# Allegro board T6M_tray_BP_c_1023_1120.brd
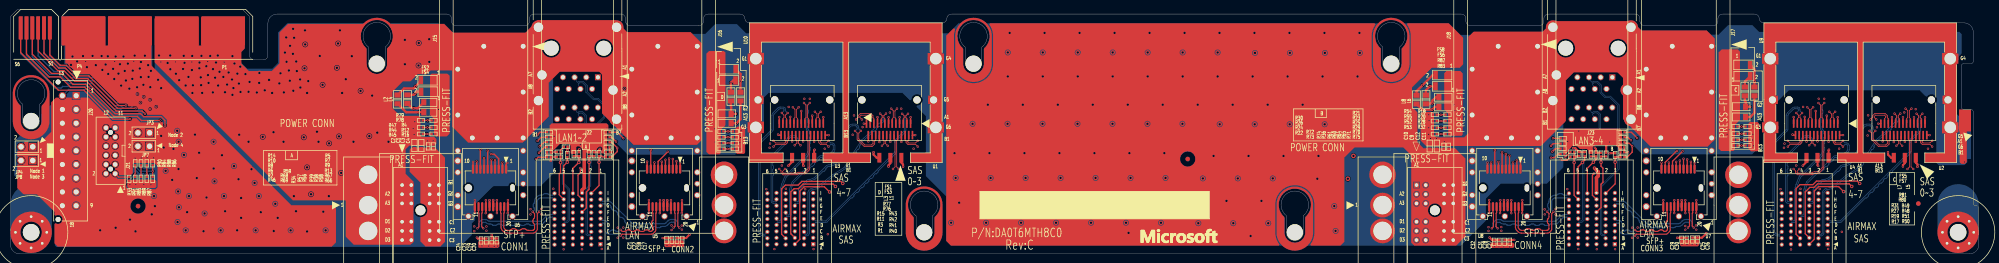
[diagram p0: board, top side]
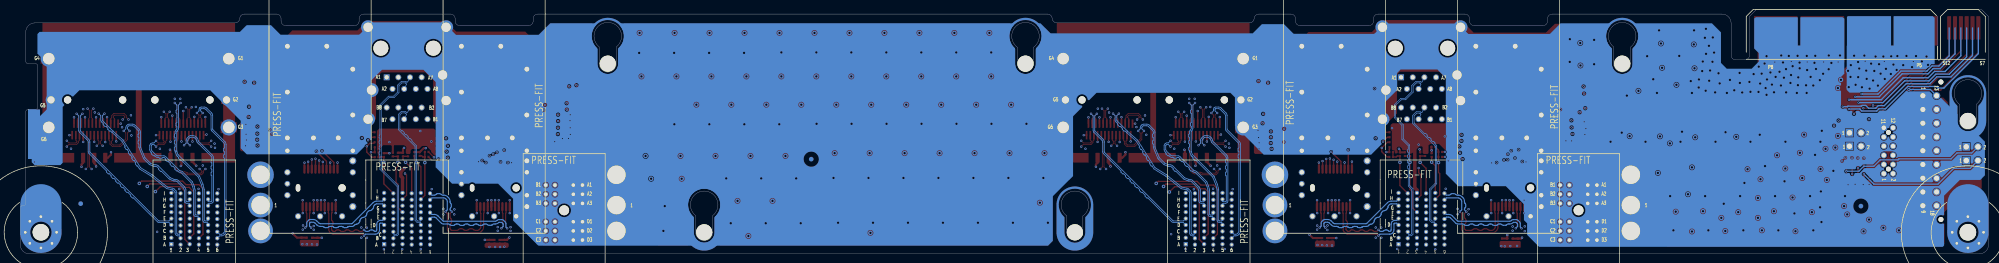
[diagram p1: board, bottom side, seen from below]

Outline 428.81 x 53.3 mm; copper layers: TOP, GND, IN1, VCC, VCC1, IN2, GND1, BOTTOM. Coordinates in mm from the lower left corner of the outline.
Outline path: 0,51.8 0,2 arc(0.59,0.59) 2,0 426.81,0 arc(428.22,0.59) 428.81,2 428.81,10 arc(428.66,10.35) 428.31,10.5 428.11,10.5 arc(427.76,10.65) 427.61,11 427.61,31 arc(427.46,31.35) 427.11,31.5 425.51,31.5 arc(425.16,31.65) 425.01,32 425.01,41 arc(425.16,41.35) 425.51,41.5 427.11,41.5 arc(427.46,41.65) 427.61,42 427.61,48.39 arc(427.02,49.8) 425.61,50.39 381.99,50.39 381.61,50.46 381.29,50.68 381.07,51 380.98,51.38 380.91,51.7 380.7,52.03 380.37,52.24 379.99,52.32 372.99,52.32 arc(372.28,52.03) 371.99,51.32 371.99,50.8 arc(371.7,50.09) 370.99,49.8 355.99,49.8 arc(355.28,50.09) 354.99,50.8 354.99,51.32 arc(354.7,52.03) 353.99,52.32 335.07,52.32 arc(334.36,52.03) 334.07,51.32 334.07,50.8 arc(333.78,50.09) 333.07,49.8 318.07,49.8 arc(317.36,50.09) 317.07,50.8 317.07,51.32 arc(316.78,52.03) 316.07,52.32 204.99,52.32 204.61,52.24 204.28,52.03 204.07,51.7 204,51.38 203.91,51 203.69,50.68 203.37,50.46 202.99,50.39 160.99,50.39 160.61,50.46 160.29,50.68 160.07,51 159.98,51.38 159.91,51.7 159.7,52.03 159.37,52.24 158.99,52.32 151.99,52.32 arc(151.28,52.03) 150.99,51.32 150.99,50.8 arc(150.7,50.09) 149.99,49.8 134.99,49.8 arc(134.28,50.09) 133.99,50.8 133.99,51.32 arc(133.7,52.03) 132.99,52.32 114.07,52.32 arc(113.36,52.03) 113.07,51.32 113.07,50.8 arc(112.78,50.09) 112.07,49.8 97.07,49.8 arc(96.36,50.09) 96.07,50.8 96.07,51.32 arc(95.78,52.03) 95.07,52.32 58.08,52.32 arc(56.67,51.73) 56.08,50.32 56.08,43.32 arc(55.79,42.61) 55.08,42.32 53.08,42.32 arc(52.37,42.61) 52.08,43.32 52.08,51.8 50.58,53.3 12.65,53.3 11.15,51.8 11.15,42.65 arc(10.8,42.3) 10.45,42.65 10.45,51.8 9.45,52.8 8.95,53.3 1.5,53.3 1,52.8 0,51.8 ; 2.65,32.64 arc(4.5,38) 6.35,32.64 6.35,29 arc(4.5,27.15) 2.65,29 2.65,32.64 ; 77.96,45.14 arc(79.81,50.5) 81.66,45.14 81.66,41.5 arc(79.81,39.65) 77.96,41.5 77.96,45.14 ; 197.3,8.26 arc(199.05,13.7) 200.8,8.26 200.8,4.7 arc(199.05,2.95) 197.3,4.7 197.3,8.26 ; 208.06,45.06 arc(209.81,50.5) 211.56,45.06 211.56,41.5 arc(209.81,39.75) 208.06,41.5 208.06,45.06 ; 277.96,8.34 arc(279.81,13.7) 281.66,8.34 281.66,4.7 arc(279.81,2.85) 277.96,4.7 277.96,8.34 ; 298.96,45.14 arc(300.81,50.5) 302.66,45.14 302.66,41.5 arc(300.81,39.65) 298.96,41.5 298.96,45.14

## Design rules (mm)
net group SFI_PORT0: nets ENET10G_1_RDN ENET10G_1_RDP ENET10G_1_TDN ENET10G_1_TDP
net group SFI_PORT1: nets ENET10G_2_RDN ENET10G_2_RDP ENET10G_2_TDN ENET10G_2_TDP
net group SFI_PORT2: nets ENET10G_3_RDN ENET10G_3_RDP ENET10G_3_TDN ENET10G_3_TDP
net group SFI_PORT3: nets ENET10G_4_RDN ENET10G_4_RDP ENET10G_4_TDN ENET10G_4_TDP
net group SMBUS-I2C_CLK: nets ENET10G_1_SCL ENET10G_2_SCL ENET10G_3_SCL ENET10G_4_SCL
net group SMBUS-I2C_DATA: nets ENET10G_1_SDA ENET10G_2_SDA ENET10G_3_SDA ENET10G_4_SDA
net group TRD1: nets ENET1G_1_MDI0N ENET1G_1_MDI0P ENET1G_1_MDI1N ENET1G_1_MDI1P ENET1G_1_MDI2N ENET1G_1_MDI2P ENET1G_1_MDI3N ENET1G_1_MDI3P
net group TRD2: nets ENET1G_2_MDI0N ENET1G_2_MDI0P ENET1G_2_MDI1N ENET1G_2_MDI1P ENET1G_2_MDI2N ENET1G_2_MDI2P ENET1G_2_MDI3N ENET1G_2_MDI3P
net group TRD3: nets ENET1G_3_MDI0N ENET1G_3_MDI0P ENET1G_3_MDI1N ENET1G_3_MDI1P ENET1G_3_MDI2N ENET1G_3_MDI2P ENET1G_3_MDI3N ENET1G_3_MDI3P
net group TRD4: nets ENET1G_4_MDI0N ENET1G_4_MDI0P ENET1G_4_MDI1N ENET1G_4_MDI1P ENET1G_4_MDI2N ENET1G_4_MDI2P ENET1G_4_MDI3N ENET1G_4_MDI3P

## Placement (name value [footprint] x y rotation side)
C1  1UF  [C0603]  89.52 23.62 270 top
C2  1UF  [C0603]  88.02 23.62 270 top
C3  0.1UF  [C0402]  91 23.44 270 top
C4  0.1UF  [C0402]  92.14 23.44 270 top
C9  1UF  [C0603]  310.75 23.52 270 top
C10  1UF  [C0603]  309.2 23.52 270 top
C11  0.1UF  [C0402]  313.32 23.37 270 top
C12  0.1UF  [C0402]  312.25 23.37 270 top
C17  0.1UF  [C0402]  146.33 3.05 90 top
C18  100PF  [C0402]  145.21 3.05 90 top
C19  0.1UF  [C0402]  104.85 2.95 90 top
C20  100PF  [C0402]  105.97 2.95 90 top
C21  0.1UF  [C0402]  142.95 3.05 90 top
C22  100PF  [C0402]  144.09 3.05 90 top
C23  0.1UF  [C0402]  103.68 2.92 90 top
C24  100PF  [C0402]  102.51 2.92 90 top
C25  0.1UF  [C0402]  366.42 3.12 90 top
C26  100PF  [C0402]  367.54 3.12 90 top
C27  0.1UF  [C0402]  326.64 2.64 90 top
C28  100PF  [C0402]  325.53 2.64 90 top
C29  0.1UF  [C0402]  364.08 3.1 90 top
C30  100PF  [C0402]  365.23 3.1 90 top
C31  0.1UF  [C0402]  323.24 2.64 90 top
C32  100PF  [C0402]  324.36 2.64 90 top
FS1  1.1A/6V  [F1206]  155.09 40.29 0 top
FS2  1.1A/6V  [F1206]  92.31 37.88 180 top
FS3  1.1A/6V  [F1206]  155.06 37.84 0 top
FS4  1.1A/6V  [F1206]  92.33 35.38 180 top
FS5  1.1A/6V  [F1206]  376.1 41.22 0 top
FS6  1.1A/6V  [F1206]  313.34 36.55 180 top
FS7  1.1A/6V  [F1206]  376.12 38.76 0 top
FS8  1.1A/6V  [F1206]  313.37 39.02 180 top
GNDPAD1  -  [GNDPAD_SMD103X189T]  425.81 29.1 0 top
GNDPAD2  -  [GNDPAD_SMD103X426T]  425.81 26.1 180 bottom
H1  -  [HOLE_C8D3-5_6B8_OB6XC3N]  199.05 4.7 180 top
H2  -  [HOLE_C8D3-5_6B8_OB6XC3N]  279.81 4.7 180 top
H3  -  [HOLE_C8D3-5_6B8_OB6XC3N]  79.81 41.5 180 top
H4  -  [HOLE_C8D3-5_6B8_OB6XC3N]  209.81 41.5 180 top
H5  -  [HOLE_C8D3-5_6B8_OB6XC3N]  4.5 29 180 top
H6  -  [HOLE_C8D3-5_6B8_OB6XC3N]  300.81 41.5 180 top
H7  GNDHOLE_8PIN  [GND_C9D3-6B9_OB6XC4-5B]  4.5 4.7 180 top
H8  GNDHOLE_8PIN  [GND_C9D3-6B9_OB6XC4-5B]  424.31 4.7 180 top
J3  CONN24_100526204555P00LF  [HSD_F24XA]  85.32 15 0 top
J5  CONN3_10044366101LF  [CON_GUIDE-M3]  298.92 10.63 0 top
J6  CONN3_10044366101LF  [CON_GUIDE-M3]  376.46 10.63 0 top
J7  CONN54_10053656101LF  [HSD_F54]  349.53 2.1 180 top
J8  CONN54_10053656101LF  [HSD_F54]  395.89 2.1 180 top
J9  CONN24_100526204555P00LF  [HSD_F24XA]  306.32 15 0 top
J11  CONN3_10044366101LF  [CON_GUIDE-M3]  77.92 10.63 0 top
J12  CONN3_10044366101LF  [CON_GUIDE-M3]  155.46 10.63 0 top
J15  SFP+ Cage  [SFP20_CAGEXA]  111.69 49.8 0 top
J16  SFP+ Cage  [SFP20_CAGEXA]  149.62 49.8 0 top
J17  SFP+ Cage  [SFP20_CAGEXA]  370.61 49.8 0 top
J18  SFP+ Cage  [SFP20_CAGEXA]  332.7 49.8 0 top
J19  GOLD44_10117936003LF  [GOLD_PWR44XA]  8.57 49.3 180 top
J20  PWR_CON_2X9  [CON_PWR2X9HXA]  14.31 34.5 0 top
J21  HEADER2X6  [HEADER2X6BH]  22.81 27.5 180 top
J22  RJ45X2  [RJ45X2XD]  123.54 44.87 180 top
J23  RJ45X2  [RJ45X2XD]  344.54 44.87 180 top
J24  CONN54_10053656101LF  [HSD_F54]  128.53 2.1 180 top
J25  CONN54_10053656101LF  [HSD_F54]  174.89 2.1 180 top
JP3  HEADER 1X2  [HEADER1X2XE]  29.03 26.41 180 top
JP4  HEADER 1X2  [HEADER1X2XE]  3.58 23.36 180 top
JP7  HEADER 1X2  [HEADER1X2XE]  29.03 23.48 180 top
JP8  HEADER 1X2  [HEADER1X2XE]  3.58 20.36 180 top
L1  BLM21PG331SN1D  [L0805]  159.05 34.32 90 top
L2  BLM21PG331SN1D  [L0805]  84.33 33.71 90 top
L3  BLM21PG331SN1D  [L0805]  156.96 34.32 90 top
L4  BLM21PG331SN1D  [L0805]  86.48 33.73 90 top
L5  BLM21PG331SN1D  [L0805]  379.93 35.43 90 top
L6  BLM21PG331SN1D  [L0805]  308.38 33.68 90 top
L7  BLM21PG331SN1D  [L0805]  377.85 35.43 90 top
L8  BLM21PG331SN1D  [L0805]  306.32 33.66 90 top
NOREF  -  []  330.37 14.39 0 top
NOREF#2  -  []  202.99 50.39 0 top
NOREF#3  -  [unnamed#2]  27.79 10.41 0 top
NOREF#4  -  []  425.01 41.5 0 top
NOREF#5  -  []  204 51.38 0 top
NOREF#6  -  []  56.08 50.32 0 top
NOREF#7  -  []  380.98 51.38 0 top
NOREF#8  -  []  4.5 4.7 0 top
NOREF#9  -  []  354.99 51.32 0 top
NOREF#10  -  []  426.61 31.5 0 top
NOREF#11  -  []  4.5 29 0 top
NOREF#12  -  []  333.07 49.8 0 top
NOREF#13  -  []  438.81 189.9 0 top
NOREF#14  -  []  424.31 4.7 0 top
NOREF#15  -  []  334.07 51.32 0 top
NOREF#16  -  []  438.81 189.9 0 top
NOREF#17  -  []  8.95 53.3 0 top
NOREF#18  -  []  79.81 41.5 0 top
NOREF#19  -  []  300.81 41.5 0 top
NOREF#20  -  []  220.29 128.22 0 top
NOREF#21  -  []  1.5 53.3 0 top
NOREF#22  -  []  159.98 51.38 0 top
NOREF#23  -  []  199.05 4.7 0 top
NOREF#24  -  []  0 51.8 0 top
NOREF#25  -  []  209.81 41.5 0 top
NOREF#26  -  []  150.99 51.32 0 top
NOREF#27  -  []  279.81 4.7 0 top
NOREF#28  -  []  0 51.8 0 top
NOREF#29  -  []  58.08 50.32 0 top
NOREF#30  -  []  -18 187.9 0 top
NOREF#31  -  []  2 0 90 top
NOREF#32  -  []  300.81 41.5 0 top
NOREF#33  -  []  236.2 10.62 0 top
NOREF#34  -  []  424.31 4.7 0 top
NOREF#35  -  []  425.01 41.5 0 top
NOREF#36  -  []  113.07 50.8 0 top
NOREF#37  -  []  496.67 20.45 0 top
NOREF#38  -  []  -10 -55.3 0 top
NOREF#39  -  []  133.99 50.8 0 top
NOREF#40  -  []  2 2 0 top
NOREF#41  -  []  96.07 50.8 0 top
NOREF#42  -  []  330.15 14.35 0 top
NOREF#43  -  []  427.31 -55.3 90 top
NOREF#44  -  []  368.29 14.39 0 top
NOREF#45  -  []  -10 189.9 0 top
NOREF#46  -  []  2 2 0 top
NOREF#47  -  []  52.08 51.8 0 top
NOREF#48  -  []  427.61 48.39 0 top
NOREF#49  -  [unnamed#2]  415.65 10.97 0 top
NOREF#50  -  [unnamed#2]  256.46 20.7 0 top
NOREF#51  -  []  438.81 -55.3 0 top
NOREF#52  -  []  4.5 29 0 top
NOREF#53  -  []  35.36 315.62 0 top
NOREF#54  -  []  246.3 2.44 0 top
NOREF#55  -  []  279.81 4.7 0 top
NOREF#56  -  []  371.99 51.32 0 top
NOREF#57  -  []  317.07 50.8 0 top
NOREF#58  -  []  11.15 51.8 0 top
NOREF#59  -  []  402.36 -62.18 0 top
NOREF#60  -  [unnamed#2]  415.65 10.95 180 bottom
NOREF#61  -  [unnamed#2]  256.49 20.65 180 bottom
NOREF#62  -  [unnamed#2]  27.81 10.41 180 bottom
R1  10K  [R0402]  154.9 22.9 180 top
R2  10K  [R0402]  117.31 22.18 0 top
R3  10K  [R0402]  154.9 24.17 180 top
R4  10K  [R0402]  92.17 29.12 0 top
R5  10K  [R0402]  130.1 26.53 180 top
R6  10K  [R0402]  117.31 23.27 0 top
R7  10K  [R0402]  130.1 25.44 180 top
R8  10K  [R0402]  117.31 24.36 0 top
R9  10K  [R0402]  130.1 24.35 180 top
R10  10K  [R0402]  117.31 25.45 0 top
R11  10K  [R0402]  154.9 25.44 180 top
R12  10K  [R0402]  92.17 27.57 0 top
R13  10K  [R0402]  130.1 23.26 180 top
R14  10K  [R0402]  117.31 26.55 0 top
R15  10K  [R0402]  154.9 26.71 180 top
R16  10K  [R0402]  92.17 26.15 0 top
R17  10K  [R0402]  375.83 23.64 180 top
R18  10K  [R0402]  313.07 30.37 0 top
R19  10K  [R0402]  375.83 24.91 180 top
R20  10K  [R0402]  313.07 28.97 0 top
R21  10K  [R0402]  351.21 26.53 180 top
R22  10K  [R0402]  338.13 21.8 0 top
R23  10K  [R0402]  351.21 25.44 180 top
R24  10K  [R0402]  338.13 22.95 0 top
R25  10K  [R0402]  351.21 24.35 180 top
R26  10K  [R0402]  338.13 24.04 0 top
R27  10K  [R0402]  375.83 26.23 180 top
R28  10K  [R0402]  313.07 27.52 0 top
R29  10K  [R0402]  351.18 23.26 180 top
R30  10K  [R0402]  338.15 25.21 0 top
R31  10K  [R0402]  375.83 27.78 180 top
R32  10K  [R0402]  313.07 26.13 0 top
R33  100  [R0402]  25.84 16.35 270 top
R34  100  [R0402]  121.32 21.55 90 top
R36  100  [R0402]  342.97 21.78 90 top
R38  100  [R0402]  127.14 21.75 90 top
R39  10K  [R0402]  126.05 21.75 270 top
R40  100  [R0402]  157.78 22.9 0 top
R41  100  [R0402]  157.78 24.17 0 top
R42  100  [R0402]  157.78 25.44 0 top
R43  100  [R0402]  157.78 26.71 0 top
R44  100  [R0402]  89.42 27.57 180 top
R45  100  [R0402]  89.42 26.15 180 top
R46  100  [R0402]  117.31 21.09 0 top
R47  100  [R0402]  89.42 29.12 180 top
R48  100  [R0402]  378.43 26.23 0 top
R49  100  [R0402]  378.43 27.78 0 top
R50  100  [R0402]  378.43 23.64 0 top
R51  100  [R0402]  378.43 24.91 0 top
R52  100  [R0402]  310.31 27.52 180 top
R53  100  [R0402]  310.31 26.13 180 top
R54  100  [R0402]  310.31 30.37 180 top
R55  100  [R0402]  310.31 28.97 180 top
R56  100  [R0402]  123.84 21.75 90 top
R57  10K  [R0402]  122.75 21.75 270 top
R58  100  [R0402]  128.23 21.75 90 top
R59  100  [R0402]  120.97 23.36 0 top
R60  100  [R0402]  345.43 21.67 90 top
R61  10K  [R0402]  344.33 21.67 270 top
R64  100  [R0402]  346.52 21.66 90 top
R65  10K  [R0402]  347.64 21.66 270 top
R66  0  [R0402]  130.15 21.14 0 top
R67  0  [R0402]  130.15 22.21 0 top
R68  0  [R0402]  119.43 22.24 180 top
R69  0  [R0402]  119.43 21.15 180 top
R70  0  [R0402]  351.18 22.16 0 top
R71  100  [R0402]  349.59 21.56 90 top
R72  0  [R0402]  340.26 22.24 180 top
R73  0  [R0402]  340.26 21.15 180 top
R74  100  [R0402]  341.77 21.79 90 top
R75  0  [R0402]  351.18 21.09 0 top
R76  0  [R0805]  156.06 28.49 180 top
R77  0  [R0805]  156.06 30.55 180 top
R78  0  [R0805]  90.98 30.9 0 top
R79  0  [R0805]  90.98 33.06 0 top
R80  0  [R0805]  377.06 29.86 180 top
R81  0  [R0805]  377.06 32.09 180 top
R82  0  [R0805]  312.14 34.17 0 top
R83  0  [R0805]  312.14 32.07 0 top
R84  10K  [R0402]  28.44 19.74 270 top
R85  3.3K  [R0402]  28.44 16.38 90 top
R86  10K  [R0402]  30.98 19.74 270 top
R87  3.3K  [R0402]  30.98 16.38 90 top
R88  10K  [R0402]  29.71 19.74 270 top
R89  3.3K  [R0402]  29.71 16.38 90 top
R90  10K  [R0402]  27.17 19.74 270 top
R91  3.3K  [R0402]  27.17 16.38 90 top
U1  MINI_SAS_CON  [CON_26S2H2D_P0-8_LDH]  191.49 28.41 180 top
U2  MINI_SAS_CON  [CON_26S2H2D_P0-8_LDH]  412.49 28.41 180 top
U3  MINI_SAS_CON  [CON_26S2H2D_P0-8_LDH]  172.49 28.41 180 top
U4  MINI_SAS_CON  [CON_26S2H2D_P0-8_LDH]  393.48 28.41 180 top
U5  SFP CONNECTOR  [CON_SFP20R]  142.49 14.39 180 top
U6  SFP CONNECTOR  [CON_SFP20R]  104.57 14.39 180 top
U7  SFP CONNECTOR  [CON_SFP20R]  363.49 14.39 180 top
U8  SFP CONNECTOR  [CON_SFP20R]  325.57 14.39 180 top
U9  MINI_SAS_CAGE  [SFP6_CAGEX2]  402.99 33.59 0 top
U10  MINI_SAS_CAGE  [SFP6_CAGEX2]  181.99 33.59 0 top

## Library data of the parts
C1-C4 C9-C12 C17-C32 = CAP_NP
FS1-FS8 = FUSE
GNDPAD1 GNDPAD2 = GNDPAD_1P
H1-H6 = HOLE_N
H7 H8 = GND_HOLE
J3 J9 = CONN24_100526204555P00LF
J5 J6 J11 J12 = CONN3_10044366101LF
J7 J8 J24 J25 = CONN54_10053656101LF
J15-J18 = SFP_CAGE
J19 = GOLD44P_10117936003LF
J20 = CON2X9_H2H
J21 = HEADER2X6_H2H
J22 J23 = RJ45X2_3
JP3 JP4 JP7 JP8 = PIN3X1_0
L1-L8 = L
R1-R34 R36 R38-R61 R64-R91 = R
U1-U4 = MINI_SAS_CON
U5-U8 = SFP_C0NN10_1
U9 U10 = MINI_SAS_CAGE

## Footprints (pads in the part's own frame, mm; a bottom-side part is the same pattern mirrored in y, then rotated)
C0402
  rect 0.457x0.508 smd: 1(0.4,0) 2(-0.4,0)
C0603
  rect 0.813x0.711 smd: 1(0.737,0) 2(-0.737,0)
CON_26S2H2D_P0-8_LDH
  round 1.6 hole 1.6 unplated: (-6,-5.18) (6,-5.18)
  rect 0.381x1.854 smd: A1(-4.6,0) A2(-3.8,0) A3(-3,0) A4(-2.2,0) A5(-1.4,0) A6(-0.6,0) A7(0.2,0) A8(1,0) A9(1.8,0) A10(2.6,0) A11(3.4,0) A12(4.2,0) A13(5,0) B1(-5,2.51) B2(-4.2,2.51) B3(-3.4,2.51) B4(-2.6,2.51) B5(-1.8,2.51) B6(-1,2.51) B7(-0.2,2.51) B8(0.6,2.51) B9(1.4,2.51) B10(2.2,2.51) B11(3,2.51) B12(3.8,2.51) B13(4.6,2.51)
CON_GUIDE-M3
  round 5.41 hole 4.013: 1(0,0) 2(0,-5.63)
  round 5.791 hole 4.013: 3(0,6.62)
CON_PWR2X9HXA
  round 1.092 hole 1.092 unplated: (-3.94,3) (-3.94,-27)
  rect 1.6x1.6 hole 1.092: 1(0,0)
  round 1.6 hole 1.092: 2(0,-3) 3(0,-6) 4(0,-9) 5(0,-12) 6(0,-15) 7(0,-18) 8(0,-21) 9(0,-24) 10(-3,0) 11(-3,-3) 12(-3,-6) 13(-3,-9) 14(-3,-12) 15(-3,-15) 16(-3,-18) 17(-3,-21) 18(-3,-24)
CON_SFP20R
  oval 0.965x1.6 hole 0.965x1.6 unplated: (-4.8,0)
  round 1.6 hole 1.6 unplated: (4.8,0)
  oval 0.508x2.032 smd: 1(-3.4,-4.1) 2(-2.6,-4.1) 3(-1.8,-4.1) 4(-1,-4.1) 5(-0.2,-4.1) 6(0.6,-4.1) 7(1.4,-4.1) 8(2.2,-4.1) 9(3,-4.1) 10(3.8,-4.1) 11(3.4,4.1) 12(2.6,4.1) 13(1.8,4.1) 14(1,4.1) 15(0.2,4.1) 16(-0.6,4.1) 17(-1.4,4.1) 18(-2.2,4.1) 19(-3,4.1) 20(-3.8,4.1)
F1206
  rect 1.016x1.803 smd: 1(0,0) 2(2.9,0)
GND_C9D3-6B9_OB6XC4-5B
  round 3.607 hole 3.607 unplated: (0,0)
  round 0.762 hole 0.559: 2(3.411,0) 3(2.412,2.412) 4(0,3.411) 5(-2.412,2.412) 6(-3.411,0) 7(-2.412,-2.412) 8(0,-3.411) 9(2.412,-2.412)
GNDPAD_SMD103X189T
  rect 2.616x4.801 smd: 1(0,0)
GNDPAD_SMD103X426T
  rect 2.616x10.82 smd: 1(0,0)
GOLD_PWR44XA
  rect 9.474x6.299 smd: P1(-37.79,0.65) P2(-27.63,0.65) P3(-17.47,0.65) P4(-7.31,0.65) P5(-7.31,0.65) P6(-17.47,0.65) P7(-27.63,0.65) P8(-37.79,0.65)
  rect 0.813x5.004 smd: S1(0,0) S2(1.27,0) S3(2.54,0) S4(3.81,0) S5(5.08,0) S6(6.35,0) S7(6.35,0) S8(5.08,0) S9(3.81,0) S10(2.54,0) S11(1.27,0) S12(0,0)
HEADER1X2XE
  rect 1.676x1.676 hole 1.168: 1(-1.27,0)
  round 1.676 hole 1.168: 2(1.27,0)
HEADER2X6BH
  round 1.067 hole 1.067 unplated: (1,9) (1,1)
  round 1.372 hole 0.965: 1(0,10) 2(2,10) 3(0,8) 4(2,8) 5(0,6) 6(2,6) 7(0,4) 8(2,4) 9(0,2) 10(2,2) 11(0,0) 12(2,0)
HOLE_C8D3-5_6B8_OB6XC3N
  round 3.505 hole 3.505 unplated: (0,0)
HSD_F24XA
  round 2.159 hole 2.159 unplated: (4,-5.5)
  rect 1.168x1.168 hole 0.762: A1(0,0)
  round 1.168 hole 0.762: A2(0,-2) A3(0,-4) A4(2,0) A5(2,-2) A6(2,-4) B1(8,0) B2(8,-2) B3(8,-4) B4(6,0) B5(6,-2) B6(6,-4) C1(8,-8) C2(8,-10) C3(8,-12) C4(6,-8) C5(6,-10) C6(6,-12) D1(0,-8) D2(0,-10) D3(0,-12) D4(2,-8) D5(2,-10) D6(2,-12)
HSD_F54
  rect 0.914x0.914 hole 0.508: A1(0,0)
  round 0.914 hole 0.508: A2(2,0.1) A3(4,0) A4(6,0.1) A5(8,0) A6(10,0.1) B1(0,-1.4) B2(2,-1.3) B3(4,-1.4) B4(6,-1.3) B5(8,-1.4) B6(10,-1.3) C1(0,-2.8) C2(2,-2.7) C3(4,-2.8) C4(6,-2.7) C5(8,-2.8) C6(10,-2.7) D1(0,-4.2) D2(2,-4.1) D3(4,-4.2) D4(6,-4.1) D5(8,-4.2) D6(10,-4.1) E1(0,-5.6) E2(2,-5.5) E3(4,-5.6) E4(6,-5.5) E5(8,-5.6) E6(10,-5.5) F1(0,-7) F2(2,-6.9) F3(4,-7) F4(6,-6.9) F5(8,-7) F6(10,-6.9) G1(0,-8.4) G2(2,-8.3) G3(4,-8.4) G4(6,-8.3) G5(8,-8.4) G6(10,-8.3) H1(0,-9.8) H2(2,-9.7) H3(4,-9.8) H4(6,-9.7) H5(8,-9.8) H6(10,-9.7) I1(0,-11.2) I2(2,-11.1) I3(4,-11.2) I4(6,-11.1) I5(8,-11.2) I6(10,-11.1)
L0805
  rect 1.118x1.372 smd: 1(0.95,0) 2(-0.95,0)
R0402
  rect 0.457x0.508 smd: 1(0.4,0) 2(-0.4,0)
R0805
  rect 1.118x1.372 smd: 1(0.95,0) 2(-0.95,0)
RJ45X2XD
  round 3.251 hole 3.251 unplated: (-5.715,0) (5.715,0)
  rect 1.295x1.295 hole 0.889: A1(-4.445,6.35)
  round 1.295 hole 0.889: A2(-3.175,8.89) A3(-1.905,6.35) A4(-0.635,8.89) A5(0.635,6.35) A6(1.905,8.89) A7(3.175,6.35) A8(4.445,8.89) B1(4.445,15.49) B2(3.175,12.95) B3(1.905,15.49) B4(0.635,12.95) B5(-0.635,15.49) B6(-1.905,12.95) B7(-3.175,15.49) B8(-4.445,12.95)
  round 3.048 hole 2.032: G1(-8.505,15.49) G2(-7.745,9.14) G3(-8.505,-4.57) G4(8.505,-4.57) G5(7.745,5.84) G6(8.505,11.43)
SFP6_CAGEX2
  rect 0.914x2.134 smd: A1(12.11,-12.625) A2(9.71,-12.625) A3(7.31,-12.625) B1(-6.9,-12.625) B2(-9.3,-12.625) B3(-11.7,-12.625)
  round 3.531 hole 2.515: G1(-19.61,9) G3(-19.61,-6) G4(19.61,9) G6(19.61,-6)
  round 2.337 hole 1.575: G2(-19.12,0) G5(19.12,0)
SFP20_CAGEXA
  round 1.549 hole 1.041: 1(0,-4.5) 2(-8.58,-4.5) 3(0,-14.5) 4(-14.25,-9.5) 5(-14.25,-19.5) 6(0,-24.5) 7(-5.68,-24.5) 8(-11.08,-24.5) 9(-14.25,-29.5) 10(-14.25,-39.5)
  round 1.346 hole 0.94: 11(0,-27.3) 12(0,-32) 13(0,-37) 14(-2.33,-41.6) 15(-7.13,-41.6) 16(-11.93,-41.6) 17(-14.25,-27.3) 18(-14.25,-32) 19(-14.25,-37)
  round 1.245 hole 0.838: 20(0,-34.5)
unnamed#2
  round 1.016 smd: (0,0)

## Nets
GND: C1.2 C2.2 C3.2 C4.2 C9.2 C10.2 C11.2 C12.2 C17.2 C18.2 C19.2 C20.2 C21.2 C22.2 C23.2 C24.2 C25.2 C26.2 C27.2 C28.2 C29.2 C30.2 C31.2 C32.2 GNDPAD1.1 GNDPAD2.1 H7.2(GND2) H7.3(GND3) H7.4(GND4) H7.5(GND5) H7.6(GND6) H7.7(GND7) H7.8(GND8) H7.9(GND9) H8.2(GND2) H8.3(GND3) H8.4(GND4) H8.5(GND5) H8.6(GND6) H8.7(GND7) H8.8(GND8) H8.9(GND9) J3.A1 J3.A2 J3.A3 J3.A4 J3.A5 J3.A6 J3.D1 J3.D2 J3.D3 J3.D4 J3.D5 J3.D6 J5.1 J5.2 J5.3 J6.1 J6.2 J6.3 J7.A2 J7.A4 J7.A6 J7.C1 J7.C3 J7.C5 J7.D2 J7.D4 J7.D6 J7.F1 J7.F5 J7.G2 J7.G6 J7.I1 J8.A2 J8.A4 J8.A6 J8.C1 J8.C3 J8.C5 J8.D2 J8.D4 J8.D6 J8.F1 J8.F3 J8.F5 J8.G2 J8.G4 J8.G6 J8.I1 J8.I3 J8.I5 J9.A1 J9.A2 J9.A3 J9.A4 J9.A5 J9.A6 J9.D1 J9.D2 J9.D3 J9.D4 J9.D5 J9.D6 J11.1 J11.2 J11.3 J12.1 J12.2 J12.3 J15.1 J15.2 J15.3 J15.4 J15.5 J15.6 J15.7 J15.8 J15.9 J15.10 J15.11 J15.12 J15.13 J15.14 J15.15 J15.16 J15.17 J15.18 J15.19 J15.20 J16.1 J16.2 J16.3 J16.4 J16.5 J16.6 J16.7 J16.8 J16.9 J16.10 J16.11 J16.12 J16.13 J16.14 J16.15 J16.16 J16.17 J16.18 J16.19 J16.20 J17.1 J17.2 J17.3 J17.4 J17.5 J17.6 J17.7 J17.8 J17.9 J17.10 J17.11 J17.12 J17.13 J17.14 J17.15 J17.16 J17.17 J17.18 J17.19 J17.20 J18.1 J18.2 J18.3 J18.4 J18.5 J18.6 J18.7 J18.8 J18.9 J18.10 J18.11 J18.12 J18.13 J18.14 J18.15 J18.16 J18.17 J18.18 J18.19 J18.20 J19.P1 J19.P2 J19.P7 J19.P8 J20.1 J20.2 J20.3 J20.4 J20.5 J20.6 J20.7 J20.8 J20.9 J21.11 J22.G1 J22.G2 J22.G3 J22.G4 J22.G5 J22.G6 J23.G1 J23.G2 J23.G3 J23.G4 J23.G5 J23.G6 J24.A2 J24.A4 J24.A6 J24.C1 J24.C3 J24.C5 J24.D2 J24.D4 J24.D6 J24.F1 J24.F5 J24.G2 J24.G6 J24.I1 J25.A2 J25.A4 J25.A6 J25.C1 J25.C3 J25.C5 J25.D2 J25.D4 J25.D6 J25.F1 J25.F3 J25.F5 J25.G2 J25.G4 J25.G6 J25.I1 J25.I3 J25.I5 R33.1 R34.1 R36.1 R38.1 R40.1 R41.1 R42.1 R43.1 R44.1 R45.1 R46.1 R47.1 R48.1 R49.1 R50.1 R51.1 R52.1 R53.1 R54.1 R55.1 R56.1 R58.1 R59.1 R60.1 R64.1 R71.1 R74.1 R85.2 R87.2 R89.2 R91.2 U1.A1(GND1) U1.A4(GND2) U1.A7(GND3) U1.A10(GND4) U1.A13(GND5) U1.B1(GND6) U1.B4(GND7) U1.B7(GND8) U1.B10(GND9) U1.B13(GND10) U2.A1(GND1) U2.A4(GND2) U2.A7(GND3) U2.A10(GND4) U2.A13(GND5) U2.B1(GND6) U2.B4(GND7) U2.B7(GND8) U2.B10(GND9) U2.B13(GND10) U3.A1(GND1) U3.A4(GND2) U3.A7(GND3) U3.A10(GND4) U3.A13(GND5) U3.B1(GND6) U3.B4(GND7) U3.B7(GND8) U3.B10(GND9) U3.B13(GND10) U4.A1(GND1) U4.A4(GND2) U4.A7(GND3) U4.A10(GND4) U4.A13(GND5) U4.B1(GND6) U4.B4(GND7) U4.B7(GND8) U4.B10(GND9) U4.B13(GND10) U5.1(VEET#1) U5.10(VEER#10) U5.11(VEER#11) U5.14(VEER#14) U5.17(VEET#17) U5.20(VEET#20) U6.1(VEET#1) U6.10(VEER#10) U6.11(VEER#11) U6.14(VEER#14) U6.17(VEET#17) U6.20(VEET#20) U7.1(VEET#1) U7.10(VEER#10) U7.11(VEER#11) U7.14(VEER#14) U7.17(VEET#17) U7.20(VEET#20) U8.1(VEET#1) U8.10(VEER#10) U8.11(VEER#11) U8.14(VEER#14) U8.17(VEET#17) U8.20(VEET#20) U9.A1(GND1) U9.A2(GND2) U9.A3(GND3) U9.B1(GND4) U9.B2(GND5) U9.B3(GND8) U9.G1 U9.G2 U9.G3 U9.G4 U9.G5 U9.G6 U10.A1(GND1) U10.A2(GND2) U10.A3(GND3) U10.B1(GND4) U10.B2(GND5) U10.B3(GND8) U10.G1 U10.G2 U10.G3 U10.G4 U10.G5 U10.G6
P3V3_10G_1_VCCR: C21.1 C22.1 L3.2 R77.2 U5.15(VCCR)
P3V3_10G_1_VCCR_L: FS3.2 L3.1
P3V3_10G_1_VCCT: C17.1 C18.1 L1.2 R76.2 U5.16(VCCT)
P3V3_10G_1_VCCT_L: FS1.2 L1.1
P3V3_10G_2_VCCR: C23.1 C24.1 L4.2 R79.2 U6.15(VCCR)
P3V3_10G_2_VCCR_L: FS4.2 L4.1
P3V3_10G_2_VCCT: C19.1 C20.1 L2.2 R78.2 U6.16(VCCT)
P3V3_10G_2_VCCT_L: FS2.2 L2.1
P3V3_10G_3_VCCR: C29.1 C30.1 L7.2 R81.2 U7.15(VCCR)
P3V3_10G_3_VCCR_L: FS7.2 L7.1
P3V3_10G_3_VCCT: C25.1 C26.1 L5.2 R80.2 U7.16(VCCT)
P3V3_10G_3_VCCT_L: FS5.2 L5.1
P3V3_10G_4_VCCR: C31.1 C32.1 L8.2 R83.2 U8.15(VCCR)
P3V3_10G_4_VCCR_L: FS8.2 L8.1
P3V3_10G_4_VCCT: C27.1 C28.1 L6.2 R82.2 U8.16(VCCT)
P3V3_10G_4_VCCT_L: FS6.2 L6.1
P3V3_BLAD1: FS1.1 FS2.1 FS3.1 FS4.1 J24.I3 R1.1 R2.1 R3.1 R4.1 R5.1 R6.1 R7.1 R8.1 R9.1 R10.1 R11.1 R12.1 R13.1 R14.1 R15.1 R16.1 R39.2 R57.2 R76.1 R77.1 R78.1 R79.1
P3V3_BLAD2: FS5.1 FS6.1 FS7.1 FS8.1 J7.I3 R17.1 R18.1 R19.1 R20.1 R21.1 R22.1 R23.1 R24.1 R25.1 R26.1 R27.1 R28.1 R29.1 R30.1 R31.1 R32.1 R61.2 R65.2 R80.1 R81.1 R82.1 R83.1
P12V: C1.1 C2.1 C3.1 C4.1 C9.1 C10.1 C11.1 C12.1 J3.B1 J3.B2 J3.B3 J3.B4 J3.B5 J3.B6 J3.C1 J3.C2 J3.C3 J3.C4 J3.C5 J3.C6 J9.B1 J9.B2 J9.B3 J9.B4 J9.B5 J9.B6 J9.C1 J9.C2 J9.C3 J9.C4 J9.C5 J9.C6 J19.P3 J19.P4 J19.P5 J19.P6 J20.11 J20.12 J20.13 J20.14 J20.15 J20.16 J20.17 J20.18 R84.2 R86.2 R88.2 R90.2
10: J20.10
AIRMAX_RSVD1: J25.B4
AIRMAX_RSVD2: J25.C4
AIRMAX_RSVD3: J25.A3
AIRMAX_RSVD4: J25.B3
AIRMAX_RSVD5: J8.B4
AIRMAX_RSVD6: J8.C4
AIRMAX_RSVD7: J8.A3
AIRMAX_RSVD8: J8.B3
BLADE1_MATED_N: J24.I5 R34.2
BLADE2_MATED_N: J7.I5 R36.2
ENET1G_1_MDI0N: J22.A2 J24.B1
ENET1G_1_MDI0P: J22.A1 J24.A1
ENET1G_1_MDI1N: J22.A6 J24.F2
ENET1G_1_MDI1P: J22.A3 J24.E2
ENET1G_1_MDI2N: J22.A5 J24.C2
ENET1G_1_MDI2P: J22.A4 J24.B2
ENET1G_1_MDI3N: J22.A8 J24.B3
ENET1G_1_MDI3P: J22.A7 J24.A3
ENET1G_2_MDI0N: J22.B2 J24.C4
ENET1G_2_MDI0P: J22.B1 J24.B4
ENET1G_2_MDI1N: J22.B6 J24.B5
ENET1G_2_MDI1P: J22.B3 J24.A5
ENET1G_2_MDI2N: J22.B5 J24.E5
ENET1G_2_MDI2P: J22.B4 J24.D5
ENET1G_2_MDI3N: J22.B8 J24.C6
ENET1G_2_MDI3P: J22.B7 J24.B6
ENET1G_3_MDI0N: J7.B1 J23.A2
ENET1G_3_MDI0P: J7.A1 J23.A1
ENET1G_3_MDI1N: J7.F2 J23.A6
ENET1G_3_MDI1P: J7.E2 J23.A3
ENET1G_3_MDI2N: J7.C2 J23.A5
ENET1G_3_MDI2P: J7.B2 J23.A4
ENET1G_3_MDI3N: J7.B3 J23.A8
ENET1G_3_MDI3P: J7.A3 J23.A7
ENET1G_4_MDI0N: J7.C4 J23.B2
ENET1G_4_MDI0P: J7.B4 J23.B1
ENET1G_4_MDI1N: J7.B5 J23.B6
ENET1G_4_MDI1P: J7.A5 J23.B3
ENET1G_4_MDI2N: J7.E5 J23.B5
ENET1G_4_MDI2P: J7.D5 J23.B4
ENET1G_4_MDI3N: J7.C6 J23.B8
ENET1G_4_MDI3P: J7.B6 J23.B7
ENET10G_1_LOS: R13.2 R67.1 U5.8(LOS)
ENET10G_1_MOD_DEF0: R9.2 R66.1 U5.6(MOD-DEF0)
ENET10G_1_RDN: J24.E1 U5.12(RD-)
ENET10G_1_RDP: J24.D1 U5.13(RD+)
ENET10G_1_RS0: R11.2 R42.2 U5.7(RATE_SELECT0)
ENET10G_1_RS1: R15.2 R43.2 U5.9(RATE_SELECT1)
ENET10G_1_SCL: J24.E3 R7.2 U5.5(MOD-DEF1)
ENET10G_1_SDA: J24.D3 R5.2 U5.4(MOD-DEF2)
ENET10G_1_TDN: J24.H1 U5.19(TD-)
ENET10G_1_TDP: J24.G1 U5.18(TD+)
ENET10G_1_TX_DIS: R3.2 R41.2 U5.3(TX_DISABLE)
ENET10G_1_TX_FAULT: R1.2 R40.2 U5.2(TX_FAULT)
ENET10G_2_LOS: R14.2 R68.1 U6.8(LOS)
ENET10G_2_MOD_DEF0: R10.2 R69.1 U6.6(MOD-DEF0)
ENET10G_2_RDN: J24.F6 U6.12(RD-)
ENET10G_2_RDP: J24.E6 U6.13(RD+)
ENET10G_2_RS0: R12.2 R44.2 U6.7(RATE_SELECT0)
ENET10G_2_RS1: R16.2 R45.2 U6.9(RATE_SELECT1)
ENET10G_2_SCL: J24.F4 R8.2 U6.5(MOD-DEF1)
ENET10G_2_SDA: J24.E4 R6.2 U6.4(MOD-DEF2)
ENET10G_2_TDN: J24.I6 U6.19(TD-)
ENET10G_2_TDP: J24.H6 U6.18(TD+)
ENET10G_2_TX_DIS: R4.2 R47.2 U6.3(TX_DISABLE)
ENET10G_2_TX_FAULT: R2.2 R46.2 U6.2(TX_FAULT)
ENET10G_3_LOS: R29.2 R70.1 U7.8(LOS)
ENET10G_3_MOD_DEF0: R25.2 R75.1 U7.6(MOD-DEF0)
ENET10G_3_RDN: J7.E1 U7.12(RD-)
ENET10G_3_RDP: J7.D1 U7.13(RD+)
ENET10G_3_RS0: R27.2 R48.2 U7.7(RATE_SELECT0)
ENET10G_3_RS1: R31.2 R49.2 U7.9(RATE_SELECT1)
ENET10G_3_SCL: J7.E3 R23.2 U7.5(MOD-DEF1)
ENET10G_3_SDA: J7.D3 R21.2 U7.4(MOD-DEF2)
ENET10G_3_TDN: J7.H1 U7.19(TD-)
ENET10G_3_TDP: J7.G1 U7.18(TD+)
ENET10G_3_TX_DIS: R19.2 R51.2 U7.3(TX_DISABLE)
ENET10G_3_TX_FAULT: R17.2 R50.2 U7.2(TX_FAULT)
ENET10G_4_LOS: R30.2 R72.1 U8.8(LOS)
ENET10G_4_MOD_DEF0: R26.2 R73.1 U8.6(MOD-DEF0)
ENET10G_4_RDN: J7.F6 U8.12(RD-)
ENET10G_4_RDP: J7.E6 U8.13(RD+)
ENET10G_4_RS0: R28.2 R52.2 U8.7(RATE_SELECT0)
ENET10G_4_RS1: R32.2 R53.2 U8.9(RATE_SELECT1)
ENET10G_4_SCL: J7.F4 R24.2 U8.5(MOD-DEF1)
ENET10G_4_SDA: J7.E4 R22.2 U8.4(MOD-DEF2)
ENET10G_4_TDN: J7.I6 U8.19(TD-)
ENET10G_4_TDP: J7.H6 U8.18(TD+)
ENET10G_4_TX_DIS: R20.2 R55.2 U8.3(TX_DISABLE)
ENET10G_4_TX_FAULT: R18.2 R54.2 U8.2(TX_FAULT)
NODE1_EN: J19.S3 J24.H2 JP4.1
NODE1_RXD: J19.S2 J24.G3
NODE1_TXD: J19.S1 J24.H3
NODE2_EN: J19.S4 J24.G5 JP3.1
NODE2_RXD: J19.S6 J24.G4
NODE2_TXD: J19.S5 J24.H4
NODE3_EN: J7.H2 J19.S10 JP8.1
NODE3_RXD: J7.G3 J19.S11
NODE3_TXD: J7.H3 J19.S12
NODE4_EN: J7.G5 J19.S9 JP7.1
NODE4_RXD: J7.G4 J19.S7
NODE4_TXD: J7.H4 J19.S8
PS_EN_PSU_N: J21.1 R33.2
SAS_BLAD1_RX1_N: J25.E1 U1.A3(RX0N)
SAS_BLAD1_RX1_P: J25.D1 U1.A2(RX0P)
SAS_BLAD1_RX2_N: J25.I2 U1.A6(RX1N)
SAS_BLAD1_RX2_P: J25.H2 U1.A5(RX1P)
SAS_BLAD1_RX3_N: J25.C2 U1.A9(RX2N)
SAS_BLAD1_RX3_P: J25.B2 U1.A8(RX2P)
SAS_BLAD1_RX4_N: J25.E3 U1.A12(RX3N)
SAS_BLAD1_RX4_P: J25.D3 U1.A11(RX3P)
SAS_BLAD1_RX5_N: J25.I4 U3.A3(RX0N)
SAS_BLAD1_RX5_P: J25.H4 U3.A2(RX0P)
SAS_BLAD1_RX6_N: J25.E5 U3.A6(RX1N)
SAS_BLAD1_RX6_P: J25.D5 U3.A5(RX1P)
SAS_BLAD1_RX7_N: J25.I6 U3.A9(RX2N)
SAS_BLAD1_RX7_P: J25.H6 U3.A8(RX2P)
SAS_BLAD1_RX8_N: J25.C6 U3.A12(RX3N)
SAS_BLAD1_RX8_P: J25.B6 U3.A11(RX3P)
SAS_BLAD1_TX1_N: J25.B1 U1.B3(TX0N)
SAS_BLAD1_TX1_P: J25.A1 U1.B2(TX0P)
SAS_BLAD1_TX2_N: J25.H1 U1.B6(TX1N)
SAS_BLAD1_TX2_P: J25.G1 U1.B5(TX1P)
SAS_BLAD1_TX3_N: J25.F2 U1.B9(TX2N)
SAS_BLAD1_TX3_P: J25.E2 U1.B8(TX2P)
SAS_BLAD1_TX4_N: J25.H3 U1.B12(TX3N)
SAS_BLAD1_TX4_P: J25.G3 U1.B11(TX3P)
SAS_BLAD1_TX5_N: J25.F4 U3.B3(TX0N)
SAS_BLAD1_TX5_P: J25.E4 U3.B2(TX0P)
SAS_BLAD1_TX6_N: J25.B5 U3.B6(TX1N)
SAS_BLAD1_TX6_P: J25.A5 U3.B5(TX1P)
SAS_BLAD1_TX7_N: J25.H5 U3.B9(TX2N)
SAS_BLAD1_TX7_P: J25.G5 U3.B8(TX2P)
SAS_BLAD1_TX8_N: J25.F6 U3.B12(TX3N)
SAS_BLAD1_TX8_P: J25.E6 U3.B11(TX3P)
SAS_BLAD2_RX1_N: J8.E1 U2.A3(RX0N)
SAS_BLAD2_RX1_P: J8.D1 U2.A2(RX0P)
SAS_BLAD2_RX2_N: J8.I2 U2.A6(RX1N)
SAS_BLAD2_RX2_P: J8.H2 U2.A5(RX1P)
SAS_BLAD2_RX3_N: J8.C2 U2.A9(RX2N)
SAS_BLAD2_RX3_P: J8.B2 U2.A8(RX2P)
SAS_BLAD2_RX4_N: J8.E3 U2.A12(RX3N)
SAS_BLAD2_RX4_P: J8.D3 U2.A11(RX3P)
SAS_BLAD2_RX5_N: J8.I4 U4.A3(RX0N)
SAS_BLAD2_RX5_P: J8.H4 U4.A2(RX0P)
SAS_BLAD2_RX6_N: J8.E5 U4.A6(RX1N)
SAS_BLAD2_RX6_P: J8.D5 U4.A5(RX1P)
SAS_BLAD2_RX7_N: J8.I6 U4.A9(RX2N)
SAS_BLAD2_RX7_P: J8.H6 U4.A8(RX2P)
SAS_BLAD2_RX8_N: J8.C6 U4.A12(RX3N)
SAS_BLAD2_RX8_P: J8.B6 U4.A11(RX3P)
SAS_BLAD2_TX1_N: J8.B1 U2.B3(TX0N)
SAS_BLAD2_TX1_P: J8.A1 U2.B2(TX0P)
SAS_BLAD2_TX2_N: J8.H1 U2.B6(TX1N)
SAS_BLAD2_TX2_P: J8.G1 U2.B5(TX1P)
SAS_BLAD2_TX3_N: J8.F2 U2.B9(TX2N)
SAS_BLAD2_TX3_P: J8.E2 U2.B8(TX2P)
SAS_BLAD2_TX4_N: J8.H3 U2.B12(TX3N)
SAS_BLAD2_TX4_P: J8.G3 U2.B11(TX3P)
SAS_BLAD2_TX5_N: J8.F4 U4.B3(TX0N)
SAS_BLAD2_TX5_P: J8.E4 U4.B2(TX0P)
SAS_BLAD2_TX6_N: J8.B5 U4.B6(TX1N)
SAS_BLAD2_TX6_P: J8.A5 U4.B5(TX1P)
SAS_BLAD2_TX7_N: J8.H5 U4.B9(TX2N)
SAS_BLAD2_TX7_P: J8.G5 U4.B8(TX2P)
SAS_BLAD2_TX8_N: J8.F6 U4.B12(TX3N)
SAS_BLAD2_TX8_P: J8.E6 U4.B11(TX3P)
SFP1_PRESENT_N: J24.I2 R58.2 R66.2 R67.2
SFP2_PRESENT_N: J24.H5 R59.2 R68.2 R69.2
SFP3_PRESENT_N: J7.I2 R70.2 R71.2 R75.2
SFP4_PRESENT_N: J7.H5 R72.2 R73.2 R74.2
SKU_PIN_BLAD1_1: J24.F3 R38.2 R39.1
SKU_PIN_BLAD1_2: J24.I4 R56.2 R57.1
SKU_PIN_BLAD2_1: J7.F3 R64.2 R65.1
SKU_PIN_BLAD2_2: J7.I4 R60.2 R61.1
N39386877: JP3.2 R84.1 R85.1
N39391900: JP4.2 R86.1 R87.1
N39395053: JP7.2 R88.1 R89.1
N39398095: JP8.2 R90.1 R91.1

Pads without a net: J21 2 3 4 5 6 7 8 9 10 12

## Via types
v1: diameter 0.508, hole 0.254, TOP to BOTTOM, 444 vias
v2: diameter 0.66, hole 0.33, TOP to BOTTOM, 1 via
v3: diameter 0.762, hole 0.381, TOP to BOTTOM, 16 vias
v4: diameter 1.016, hole 0.508, TOP to BOTTOM, 297 vias

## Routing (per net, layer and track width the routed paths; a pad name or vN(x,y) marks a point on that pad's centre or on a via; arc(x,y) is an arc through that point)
GND: length 147.2
  TOP w0.29: U7.10 v1(359.69,19.91) ; v1(324.54,8.89) 324.57,8.92 U8.14 v1(324.57,11.71) ; U3.B10 v1(170.29,24.51) ; v1(410.29,24.4) 410.3,24.4 U2.B10 ; U2.B4 415.09,24.42 v1(415.09,24.42) ; U2.A7 412.3,29.79 v1(412.29,29.79) ; v1(141.45,8.89) 141.49,8.93 U5.14 v1(141.49,11.71) ; v1(139.09,8.89) U5.11 v1(139.09,11.71) ; U3.A4 v1(174.68,30.15) ; v1(409.89,29.82) 409.9,29.82 U2.A10 ; v1(360.09,11.71) U7.11 v1(360.09,8.89) ; U6.10 v1(100.77,20.05) ; v1(364.89,8.89) U7.17 v1(364.89,11.71) ; U1.A10 v1(188.89,29.82) ; v1(362.46,8.89) 362.49,8.92 U7.14 v1(362.49,11.71) ; v1(143.89,11.71) U5.17 v1(143.89,8.89) ; v1(329.34,8.89) 329.37,8.92 U8.20 v1(329.37,11.71) ; v1(103.53,8.89) 103.57,8.93 U6.14 v1(103.57,11.71) ; v1(407.89,24.53) 407.9,24.53 U2.B13 ; U3.A7 v1(172.29,31.17) ; v1(108.25,19.84) 107.97,19.55 U6.1 ; v1(367.26,8.89) 367.29,8.92 U7.20 v1(367.29,11.71) ; U8.1 v1(328.97,20.11) ; U4.A1 v1(398.08,29.82) ; U2.A4 v1(414.69,29.79) ; v1(322.17,11.71) U8.11 v1(322.17,8.89) ; U1.B7 v1(191.69,24.43) ; U4.A4 v1(395.68,30.15) ; v1(146.29,11.71) U5.20 146.29,8.93 v1(146.25,8.89) ; U4.A13 v1(388.48,29.84) ; U4.B13 388.37,25.9 v1(388.23,26.04) ; v1(108.37,11.71) U6.20 108.37,8.93 v1(108.33,8.89) ; U2.B1 v1(418.11,25.9) ; U4.B1 v1(399.24,25.9) ; U4.A10 v1(390.88,29.89) ; U1.B10 v1(189.3,24.4) ; U5.1 v1(145.89,19.91) ; v1(167.23,26.04) 167.37,25.9 U3.B13 ; v1(326.97,11.71) U8.17 v1(326.97,8.89) ; v1(101.17,11.71) U6.11 v1(101.17,8.89) ; U4.A7 v1(393.28,31.17) ; U7.1 v1(366.89,19.89) ; U2.A13 v1(406.92,28.41) ; U1.B13 v1(186.89,24.53) ; U4.B10 v1(391.28,24.51) ; U4.B4 v1(396.08,24.46) ; U8.10 v1(321.77,19.89) ; U2.B7 v1(412.69,24.43) ; U3.A13 v1(167.49,29.84) ; U1.B1 v1(197.11,25.9) ; v1(105.97,11.71) U6.17 v1(105.97,8.89) ; U4.B7 v1(393.68,24.52) ; U3.A10 v1(169.89,29.89) ; U1.A7 v1(191.3,29.79) ; U3.B7 v1(172.68,24.52) ; U3.B4 v1(175.08,24.46) ; U2.A1 v1(417.09,29.79) ; U3.B1 v1(178.24,25.9) ; U1.A1 v1(196.09,29.79) ; U1.A4 v1(193.69,29.79) ; U5.10 v1(138.69,20.12) ; U1.A13 v1(185.92,28.41) ; U3.A1 v1(177.08,29.82) ; U1.B4 v1(194.09,24.42)
  TOP w0.356: v1(26.01,15.14) 25.84,15.31 R33.1
  TOP w0.457: R56.1 123.84,22.7 v1(123.95,22.81) ; U9.B3 391.29,20.05 v1(390.47,19.23) ; v1(340.46,23.06) 340.9,23.06 R74.1 341.78,22.18 R36.1 ; v1(412.29,19.08) 412.29,19.35 412.7,19.77 U9.A2 ; U9.A1 415.1,19.87 415.46,19.51 v1(415.46,19) ; U10.B3 170.29,20.05 v1(169.47,19.23) ; v1(175.19,22.71) 175.09,22.61 U10.B1 ; v1(194.46,19) 194.46,19.51 194.1,19.87 U10.A1 ; U10.A3 188.71,20.96 188.04,21.64 v1(188.04,22.17) ; U9.B2 393.69,19.32 v1(393.83,19.18) ; v1(345.19,23.11) 345.43,22.87 R60.1 345.44,22.06 R64.1 ; U9.A3 409.71,20.96 409.04,21.64 v1(409.04,22.17) ; U10.B2 172.69,19.31 v1(172.8,19.2) ; R38.1 R58.1 128.23,22.69 v1(128.45,22.91) ; v1(396.19,22.71) 396.09,22.61 U9.B1 ; R59.1 121.37,22.63 v1(121.32,22.58) R34.1 ; U10.A2 191.7,19.77 191.29,19.35 v1(191.29,19.08) ; R46.1 v1(117.71,20.29) ; R71.1 v1(348.39,21.96)
  vias: v1(27.3,15.11) v1(29.06,15.16) v1(30.61,15.09) v1(32.77,41.86) v1(35.92,41.86) v1(39.5,41.86) v1(42.98,41.96) v1(46.56,41.83) v1(87.73,27.33) v1(87.93,26.04) v1(88.09,28.83) v1(90.83,24.64) v1(92.08,24.66) v1(101.04,5.99) v1(101.04,4.95) v1(102.72,1.73) v1(103.68,5.97) v1(103.68,5.05) v1(104.19,1.7) v1(105.38,1.65) v1(106.15,1.7) v1(113.28,9.75) v1(113.28,8.61) v1(115.67,9.8) v1(115.67,8.64) v1(118.26,14.2) v1(120.52,0.99) v1(124.51,1.02) v1(128.83,1.07) v1(132.31,5.71) v1(132.28,3.51) v1(133.5,5.74) v1(133.5,3.53) v1(143.03,1.83) v1(144.02,6.2) v1(144.04,5.21) v1(144.15,1.85) v1(145.16,1.91) v1(146.2,1.93) v1(146.25,6.17) v1(146.28,5.28) v1(158.9,24.23) v1(158.93,22.89) v1(159.03,25.37) v1(159.16,26.95) v1(164.67,14.12) v1(165.38,23.14) v1(165.48,24.05) v1(166.42,1.04) v1(168.05,19.28) v1(168.94,14.2) v1(169.54,32.05) v1(172.95,33.83) v1(173.13,14.1) v1(174.14,33.83) v1(174.96,1.04) v1(177.39,22.94) v1(183.49,25.98) v1(183.77,30.2) v1(185.65,27.66) v1(191.59,30.84) v1(194.06,31.67) v1(196.75,22.94) v1(308.99,30.35) v1(309.04,29.06) v1(308.99,27.51) v1(308.97,26.06) v1(309.37,25.17) v1(310.69,25.15) v1(312.37,24.49) v1(322,5.82) v1(322,5) v1(323.34,1.55) v1(324.28,1.5) v1(324.79,5.84) v1(324.79,5.03) v1(325.35,1.5) v1(326.59,1.5) v1(334.23,9.7) v1(334.26,8.61) v1(336.62,9.8) v1(336.62,8.59) v1(339.17,14.12) v1(341.55,1.04) v1(345.59,1.02) v1(349.58,1.02) v1(353.31,5.71) v1(353.28,3.51) v1(354.5,5.74) v1(354.5,3.53) v1(364.16,2.03) v1(364.87,6.07) v1(364.87,5.26) v1(365.25,2.06) v1(366.37,2.08) v1(367.21,6.2) v1(367.26,5.28) v1(367.36,2.11) v1(379.53,24.84) v1(379.6,26.09) v1(379.65,28.24) v1(379.73,23.57) v1(385.62,14.12) v1(386.38,23.14) v1(386.48,24.05) v1(387.91,0.97) v1(389.05,19.28) v1(389.97,14.17) v1(390.55,32.05) v1(393.95,33.83) v1(394.16,14.15) v1(395.14,33.83) v1(395.99,1.07) v1(398.39,22.94) v1(404.6,25.83) v1(404.7,30.23) v1(406.63,27.61) v1(412.57,30.86) v1(415.08,31.57) v1(417.75,22.94) v1(425.73,20.04) v4(31.27,12.6) v4(32.36,43.28) v4(33.81,18.11) v4(34.24,41.66) v4(34.8,43.28) v4(34.82,40.28) v4(36.04,39.29) v4(36.32,26.85) v4(36.4,6.93) v4(36.53,13.61) v4(36.63,24.46) v4(36.7,10.16) v4(36.75,37.9) v4(37.59,40.34) v4(37.74,43.21) v4(37.8,21.59) v4(37.92,41.68) v4(38.18,36.73) v4(38.18,5.13) v4(38.76,38.61) v4(38.89,12.6) v4(39.52,40.11) v4(39.6,43.18) v4(39.62,35.1) v4(39.75,36.78) v4(41.15,40.49) v4(41.17,41.73) v4(41.45,38.51) v4(41.53,36.8) v4(41.61,43.21) v4(41.76,35.1) v4(42.29,8.81) v4(42.67,40.94) v4(43.03,39.01) v4(43.15,37.29) v4(43.51,43.18) v4(44.12,40.31) v4(44.09,35.23) v4(44.25,24.46) v4(44.45,15.82) v4(44.58,38.43) v4(44.78,41.76) v4(45.16,43.28) v4(45.24,36.73) v4(45.54,39.73) v4(45.8,5.13) v4(46.38,38.61) v4(46.51,12.6) v4(46.74,35.26) v4(47.19,36.93) v4(47.52,39.57) v4(48.26,38.05) v4(48.36,43.13) v4(48.36,34.7) v4(48.56,36.17) v4(48.69,19.15) v4(48.79,41.53) v4(49.43,39.32) v4(49.76,37.16) v4(49.83,25.98) v4(50.06,40.84) v4(50.11,35.33) v4(51.18,39.22) v4(51.87,35.36) v4(51.87,24.46) v4(52.1,37.52) v4(53.19,15.47) v4(53.42,5.13) v4(53.67,35.2) v4(54.13,12.6) v4(54.23,39.47) v4(54.18,37.29) v4(55.4,35.69) v4(56.34,37.95) v4(57,35.1) v4(57.3,26.54) v4(57.68,10.92) v4(58.57,37.19) v4(58.83,39.4) v4(59.49,24.46) v4(59.56,35.23) v4(59.79,43.92) v4(60.07,47.22) v4(60.15,41.91) v4(60.66,40.01) v4(60.91,45.39) v4(60.86,37.77) v4(61.04,5.13) v4(61.54,43.64) v4(61.57,49.1) v4(61.62,35.59) v4(61.75,12.6) v4(61.8,47.14) v4(62.26,41.96) v4(62.38,39.88) v4(63.09,38.05) v4(63.14,36.3) v4(64.16,48.77) v4(64.62,35.1) v4(64.87,37.69) v4(66.78,26.64) v4(67.11,24.46) v4(67.39,43.18) v4(68.66,5.13) v4(69.37,12.6) v4(71.78,48.77) v4(72.24,35.1) v4(73.05,38.1) v4(74.37,43.13) v4(74.73,24.46) v4(78.79,34.52) v4(79.91,26.44) v4(82.35,24.46) v4(85.93,46.69) v4(85.93,41.38) v4(91.21,46.84) v4(91.24,41.88) v4(204.93,6.78) v4(205.92,16.56) v4(209.6,28.37) v4(212.55,6.78) v4(213.54,16.56) v4(217.22,28.37) v4(217.27,43.94) v4(220.17,6.78) v4(221.16,16.56) v4(224.84,28.37) v4(224.89,43.94) v4(227.79,6.78) v4(228.78,16.56) v4(232.51,43.94) v4(232.46,28.37) v4(235.41,6.78) v4(236.4,16.56) v4(240.13,43.94) v4(240.08,28.37) v4(243.03,6.78) v4(244.02,16.56) v4(247.7,28.37) v4(247.75,43.94) v4(250.65,6.78) v4(251.64,16.56) v4(255.32,28.37) v4(255.37,43.94) v4(258.78,6.68) v4(259.77,16.46) v4(262.99,43.94) v4(263.45,28.27) v4(266.4,6.68) v4(267.39,16.46) v4(271.12,43.84) v4(271.07,28.27) v4(274.02,6.68) v4(275.01,16.46) v4(278.74,43.84) v4(278.69,28.27) v4(286.31,28.27) v4(286.36,43.84) v4(288.39,10.41) v4(288.7,5) v4(293.98,43.84)
P3V3_10G_1_VCCR: length 60
  TOP w0.457: v1(142.09,3.45) C21.1 C22.1 ; U5.15 v1(142.29,11.71)
  TOP w0.508: L3.2 156.96,32.05 157.01,32.01 R77.2 v1(158.04,30.55)
  IN1 w0.457: v1(158.04,30.55) 158.04,29.45 155.57,26.99 155.57,23.57 150.66,18.66 150.66,7.99 146.51,3.84 142.48,3.84 v1(142.09,3.45)
  IN2 w0.457: v1(142.29,11.71) 142.29,11.89 141.86,12.32 138.76,12.32 137.92,11.48 137.92,9.93 136.63,8.64 136.63,7.7 140.87,3.45 v1(142.09,3.45)
P3V3_10G_1_VCCR_L: length 3.3
  TOP w0.508: FS3.2 157.46,37.84 v1(156.96,37.34) L3.1
P3V3_10G_1_VCCT: length 67.2
  TOP w0.457: U5.16 v1(143.09,11.71) ; C18.1 C17.1 147.2,3.45 v1(147.93,4.18)
  TOP w0.508: L1.2 159.05,29.38 v1(158.16,28.49) R76.2
  IN1 w0.457: v1(147.93,4.18) 151.42,7.67 151.42,18.3 155.12,22 156.47,22 156.97,22.5 156.97,27.3 v1(158.16,28.49)
  IN2 w0.457: v1(147.93,4.18) 146.39,2.64 140.59,2.64 135.86,7.37 135.86,9.02 137.13,10.29 137.13,11.79 138.53,13.18 142.14,13.18 143.09,12.23 v1(143.09,11.71)
P3V3_10G_1_VCCT_L: length 5.5
  TOP w0.508: L1.1 v1(159.05,37.69) 159.05,39.23 FS1.2
P3V3_10G_2_VCCR: length 58.9
  TOP w0.457: v1(101.63,3.53) 101.83,3.32 C24.1 C23.1 ; U6.15 v1(104.37,11.71)
  TOP w0.508: R79.2 88.75,31.78 v1(87.86,31.78) 87.49,31.78 L4.2
  IN1 w0.457: v1(101.63,3.53) 100.51,3.53 97.97,6.07 97.97,7.02 95.38,9.62 95.38,25.49 90.73,30.14 88.76,30.14 87.86,31.04 v1(87.86,31.78)
  IN2 w0.457: v1(101.63,3.53) 101.42,3.53 98.65,6.3 98.65,8.69 100,10.03 100,11.48 100.91,12.4 103.96,12.4 104.37,11.99 v1(104.37,11.71)
P3V3_10G_2_VCCR_L: length 3.2
  TOP w0.508: FS4.2 88.52,35.38 v1(88.11,34.97) 87.82,34.68 L4.1
P3V3_10G_2_VCCT: length 69.3
  TOP w0.457: U6.16 v1(105.17,11.73) ; C20.1 C19.1 v1(104.85,4.11)
  TOP w0.508: L2.2 86.19,30.9 v1(89.08,30.9) R78.2
  IN1 w0.457: v1(104.85,4.11) 104.62,4.34 100.79,4.34 98.73,6.4 98.73,7.34 96.19,9.88 96.19,25.75 91.05,30.9 v1(89.08,30.9)
  IN2 w0.457: v1(104.85,4.11) 103.48,2.74 101.07,2.74 97.87,5.94 97.87,9.02 99.24,10.39 99.24,11.84 100.58,13.18 104.39,13.18 105.17,12.41 v1(105.17,11.73)
P3V3_10G_2_VCCT_L: length 6.5
  TOP w0.508: L2.1 85.77,36.09 87.81,36.09 v1(88.23,36.51) 89.41,37.69 FS2.2
P3V3_10G_3_VCCR: length 61.2
  TOP w0.457: C30.1 C29.1 v1(363.1,3.5) ; U7.15 v1(363.29,11.71)
  TOP w0.508: L7.2 377.85,33.32 378.01,33.16 R81.2 v1(378.98,32.09)
  IN1 w0.457: v1(378.98,32.09) 378.98,30.87 376.5,28.4 376.5,23.2 371.76,18.46 371.76,7.98 368.35,4.57 364.17,4.57 v1(363.1,3.5)
  IN2 w0.457: v1(363.1,3.5) 361.82,3.5 357.63,7.7 357.63,8.64 358.92,9.93 358.92,11.48 359.76,12.32 362.86,12.32 363.29,11.89 v1(363.29,11.71)
P3V3_10G_3_VCCR_L: length 2.9
  TOP w0.508: L7.1 v1(377.85,37.34) 377.85,37.59 FS7.2
P3V3_10G_3_VCCT: length 67.9
  TOP w0.457: C25.1 C26.1 368.52,3.52 v1(369.47,4.47) ; U7.16 v1(364.09,11.71)
  TOP w0.508: R80.2 v1(379.04,29.86) 379.93,30.75 L5.2
  IN1 w0.457: v1(379.04,29.86) 377.8,28.62 377.8,23.42 372.52,18.14 372.52,7.53 v1(369.47,4.47)
  IN2 w0.457: v1(364.09,11.71) 364.09,12.23 363.14,13.18 359.53,13.18 358.13,11.79 358.13,10.29 356.86,9.02 356.86,7.37 361.51,2.72 367.72,2.72 v1(369.47,4.47)
P3V3_10G_3_VCCT_L: length 5.2
  TOP w0.508: L5.1 v1(379.93,37.54) 379.93,40.29 FS5.2
P3V3_10G_4_VCCR: length 58.9
  TOP w0.457: v1(322.25,3.56) 322.76,3.05 322.76,3.04 C31.1 C32.1 ; U8.15 v1(325.37,11.73)
  TOP w0.508: L8.2 307.56,31.47 v1(309.73,31.47) 310.32,32.07 R83.2
  IN1 w0.457: v1(322.25,3.56) 321.17,3.56 316.55,8.17 316.55,22.81 312.27,27.09 312.27,30.6 311.39,31.47 v1(309.73,31.47)
  IN2 w0.457: v1(322.25,3.56) 319.55,6.25 319.55,8.56 321.15,10.16 321.15,11.61 321.91,12.37 324.96,12.37 325.37,11.96 v1(325.37,11.73)
P3V3_10G_4_VCCR_L: length 6.5
  TOP w0.508: L8.1 306.32,35.48 v1(307.64,36.8) 309.86,39.02 FS8.2
P3V3_10G_4_VCCT: length 72.3
  TOP w0.457: U8.16 v1(326.17,11.71) ; C28.1 C27.1 v1(327.6,3.04)
  TOP w0.508: R82.2 310.53,34.17 309.78,33.43 v1(309.78,32.87) 309.33,32.87 309.19,32.73 L6.2
  IN1 w0.457: v1(309.78,32.87) 311.07,32.87 313.08,30.86 313.08,27.36 317.31,23.12 317.31,8.49 321.49,4.32 326.33,4.32 v1(327.6,3.04)
  IN2 w0.457: v1(326.17,11.71) 326.17,12.38 325.39,13.16 321.58,13.16 320.29,11.86 320.29,10.41 318.76,8.89 318.76,5.9 321.94,2.72 327.28,2.72 v1(327.6,3.04)
P3V3_10G_4_VCCT_L: length 3.5
  TOP w0.508: L6.1 308.38,35.71 v1(309.22,36.55) FS6.2
P3V3_BLAD1: length 11.1
  TOP w0.762: J24.I3 124.53,13.94 124.99,14.4 124.99,22.99 v1(124.16,23.83)
  vias: v1(93.27,31.5) v1(118.44,25.63) v1(129.95,27.43) v1(153.47,27.28) v1(153.52,24.38)
P3V3_BLAD2: length 18
  TOP w0.457: v1(348.39,24.38) 347.64,23.64 R65.2
  TOP w0.762: J7.I3 345.53,16.59 345.9,16.95 345.9,17.91 v1(345.08,18.72)
  IN2 w0.635: v1(341.66,26.8) 343.48,24.97 343.48,20.32 v1(345.08,18.72)
  vias: v1(314.48,32.49) v1(314.68,31.32) v1(339.24,24.51) v1(373.99,26.09) v1(374.45,27.08)
P12V:
  vias: v1(16.38,41.96) v1(22.71,41.99) v1(26.87,42.01) v1(27.17,20.86) v1(28.49,20.91) v1(29.76,20.97) v1(31.18,20.94) v1(31.89,20.23) v1(133.76,36.07) v4(13.18,41.22) v4(13.51,43.05) v4(14.53,41.99) v4(15.8,43.15) v4(16.66,40.74) v4(17.88,43.18) v4(18.59,41.17) v4(19.53,5.13) v4(19.86,43.15) v4(20.02,40.13) v4(20.73,41.3) v4(21.21,43.1) v4(21.29,39.24) v4(22.35,40.36) v4(22.61,38.15) v4(22.91,43.05) v4(22.91,5.69) v4(23.52,39.32) v4(23.85,41.38) v4(24.1,36.7) v4(24.61,43.05) v4(24.89,39.9) v4(25.15,37.82) v4(25.58,41.5) v4(25.91,36.04) v4(26.04,7.47) v4(26.54,38.18) v4(26.64,39.98) v4(27.05,43.26) v4(27.23,4.9) v4(27.58,36.35) v4(28.17,40.44) v4(28.42,41.86) v4(28.4,38.56) v4(28.96,36.88) v4(29.29,43.23) v4(30,41.17) v4(30.07,38.61) v4(30.45,36.37) v4(30.61,39.93) v4(30.78,8.61) v4(31.47,10.41) v4(32.16,37.97) v4(32.82,36.17) v4(32.82,25.73) v4(33.38,23.19) v4(35.23,16.13) v4(35.51,22.91) v4(36.6,18.52) v4(38.48,9.09) v4(40.18,26.01) v4(40.59,16.54) v4(41.1,22.05) v4(42.06,4.93) v4(42.7,12.29) v4(44.27,18.62) v4(46.08,21.51) v4(46.76,9.3) v4(49.38,5.13) v4(49.68,16.28) v4(50.24,12.19) v4(50.24,7.85) v4(52.5,18.47) v4(54.53,9.09) v4(54.97,25.53) v4(57.35,4.98) v4(58.22,7.85) v4(62.2,9.3) v4(63.91,25.43) v4(64.06,40.49) v4(64.21,45.69) v4(64.62,18.87) v4(64.62,4.88) v4(65.48,13) v4(68,36.88) v4(68.15,9.19) v4(69.42,24.1) v4(71.12,40.59) v4(71.37,45.9) v4(71.58,25.63) v4(72.03,17.65) v4(76.28,35.56) v4(78.18,25.68) v4(88.9,41.1) v4(88.95,46) v4(205.66,21.97) v4(206.68,11.15) v4(212.93,32.54) v4(213.28,21.97) v4(217.27,38.71) v4(217.68,48.21) v4(220.55,32.54) v4(220.9,21.97) v4(224.89,38.71) v4(225.3,48.21) v4(228.17,32.54) v4(228.52,21.97) v4(232.51,38.71) v4(232.92,48.21) v4(235.79,32.54) v4(236.14,21.97) v4(240.13,38.71) v4(240.54,48.21) v4(243.41,32.54) v4(243.59,4.57) v4(243.76,21.97) v4(247.75,38.71) v4(248.16,48.21) v4(251.03,32.54) v4(251.38,21.97) v4(255.37,38.71) v4(255.78,48.21) v4(258.65,32.54) v4(262.1,21.36) v4(262.99,38.71) v4(263.4,48.21) v4(264.92,11.56) v4(266.27,32.54) v4(269.72,21.36) v4(270.18,3.89) v4(270.61,38.71) v4(271.02,48.21) v4(272.54,11.56) v4(273.89,32.54) v4(277.34,21.36) v4(278.23,38.71) v4(278.64,48.21) v4(281.51,32.54) v4(284.71,16.38) v4(284.96,21.36) v4(285.85,38.71) v4(286.26,48.21) v4(291.36,16.38) v4(292.58,21.36) v4(293.47,38.71) v4(293.88,48.21)
10: length 6.6
  BOTTOM w0.29: v2(17.37,35.86) 12.67,35.86 J20.10
AIRMAX_RSVD1: length 25.3
  TOP w0.29: J25.B4 168,4.29 168,14.18 168.83,15.01 171.62,15.01 172.42,15.81 180.89,15.81 v3(181.33,15.37)
AIRMAX_RSVD2: length 10.2
  IN1 w0.183: v1(178.08,4.29) 176.76,5.61 174.27,5.61 174.14,5.48 172.52,5.48 172.42,5.59 169.68,5.59 J25.C4
AIRMAX_RSVD3: length 19.4
  TOP w0.29: J25.A3 171.96,3.17 171.96,13.68 172.91,14.62 177.33,14.62 v3(178.46,13.49)
AIRMAX_RSVD4: length 21
  TOP w0.29: J25.B3 170.01,4.38 170.01,13.51 170.69,14.2 171.64,14.2 172.66,15.22 179.22,15.22 v3(179.73,14.71)
AIRMAX_RSVD5: length 25.9
  TOP w0.29: J8.B4 389,4.29 389,14.22 389.87,15.1 392.68,15.1 393.45,15.86 402.37,15.86 v3(402.87,15.37)
AIRMAX_RSVD6: length 9.9
  IN1 w0.183: J8.C4 390.45,4.8 391.26,5.61 393.09,5.61 393.22,5.48 395.2,5.48 395.3,5.59 398.2,5.59 v1(398.98,4.8)
AIRMAX_RSVD7: length 19.3
  TOP w0.29: J8.A3 392.96,3.17 392.96,13.7 393.94,14.67 398.28,14.67 v3(399.36,13.59)
AIRMAX_RSVD8: length 21.5
  TOP w0.29: J8.B3 391.01,4.38 391.01,13.51 392,14.5 392.93,14.5 393.69,15.27 400.58,15.27 v3(401.14,14.71)
BLADE1_MATED_N: length 8.2
  TOP w0.29: J24.I5 120.53,19.23 v3(121.32,20.02) R34.2
BLADE2_MATED_N: length 8.7
  TOP w0.29: R36.2 342.97,20.44 v3(342.47,19.94) 341.53,19 J7.I5
ENET1G_1_MDI0N: length 40.1
  IN2 w0.152: J24.B1 128.53,3.14 128.67,3 130.05,3 130.84,3.78 130.84,15.91 130.66,16.09 130.66,16.54 130.84,16.72 130.84,17.18 130.66,17.36 130.66,17.81 130.84,17.99 130.84,18.45 130.66,18.63 130.66,19.08 130.84,19.26 130.84,19.85 129.54,21.14 129.54,25.79 128.14,27.19 128.14,29.86 128.93,30.65 128.93,35.5 127.47,36.96 127.39,37 127.19,36.93 J22.A2
ENET1G_1_MDI0P: length 40.8
  IN2 w0.152: J24.A1 128.53,2.48 128.65,2.6 130.22,2.6 131.24,3.62 131.24,20.02 129.95,21.31 129.95,25.96 128.55,27.36 128.55,29.69 129.34,30.48 129.34,35.67 127.71,37.29 127.57,37.36 127.5,37.57 J22.A1
ENET1G_1_MDI1N: length 33.3
  IN2 w0.152: J24.F2 126.53,8.64 126.67,8.5 127.18,8.5 127.43,8.76 127.43,21.37 127,21.8 127,25.99 125.35,27.64 125.35,30.17 126.48,31.3 126.48,33.37 124.98,34.87 123.8,34.87 122.69,35.98 J22.A6
ENET1G_1_MDI1P: length 33.8
  IN2 w0.152: J22.A3 125.44,34.99 126.89,33.54 126.89,31.13 125.76,30 125.76,27.81 127.41,26.16 127.41,21.97 127.84,21.54 127.84,8.59 127.35,8.1 126.67,8.1 126.53,7.96 J24.E2
ENET1G_1_MDI2N: length 41.7
  BOTTOM w0.147: J22.A5 123.4,37.52 123.6,37.45 123.73,37.52 123.82,37.61 124.78,37.61 125.65,36.73 125.65,35.38 127.1,33.93 128.04,33.93 129.46,32.51 129.46,29.69 127.81,28.04 127.81,24.99 126.42,23.6 126.42,22.86 126.57,22.71 126.57,22.27 126.42,22.11 126.42,21.67 126.57,21.52 126.57,21.08 126.42,20.93 126.42,20.48 126.57,20.33 126.57,19.89 126.42,19.74 126.42,19.29 126.57,19.14 126.57,18.7 126.42,18.55 126.42,14.81 125.69,14.08 125.69,4.4 125.84,4.25 126.35,4.25 126.53,4.43 J24.C2
ENET1G_1_MDI2P: length 41
  BOTTOM w0.147: J24.B2 126.53,3.75 126.33,3.95 125.71,3.95 125.38,4.27 125.38,14.21 126.11,14.93 126.11,23.72 127.51,25.12 127.51,28.17 129.16,29.82 129.16,32.38 127.91,33.63 126.98,33.63 125.35,35.26 125.35,36.6 124.65,37.3 123.95,37.3 123.91,37.27 123.74,37.18 123.67,36.98 J22.A4
ENET1G_1_MDI3N: length 55.1
  IN1 w0.152: J24.B3 124.53,3.1 124.43,3 123.88,3 123.73,3.16 123.73,14.41 125.76,16.43 125.76,25.23 129.67,29.14 129.67,33.71 129.41,33.96 129.41,39.42 128.65,40.18 119.82,40.18 118.85,39.21 118.85,37.69 119.3,37.23 119.5,37.14 119.57,36.93 J22.A8
ENET1G_1_MDI3P: length 54.4
  IN1 w0.152: J22.A7 119.88,37.57 119.68,37.5 119.54,37.57 119.25,37.86 119.25,39.04 119.99,39.78 128.48,39.78 129.01,39.25 129.01,33.79 129.26,33.54 129.26,29.31 125.35,25.4 125.35,22.68 125.2,22.53 125.2,22.07 125.35,21.92 125.35,21.46 125.2,21.31 125.2,20.85 125.35,20.7 125.35,20.25 125.2,20.09 125.2,19.64 125.35,19.48 125.35,19.03 125.2,18.87 125.2,18.42 125.35,18.26 125.35,16.6 123.32,14.58 123.32,2.99 123.71,2.6 124.38,2.6 124.53,2.44 J24.A3
ENET1G_2_MDI0N: length 33.3
  IN2 w0.152: J22.B2 119.88,30.97 119.68,30.9 119.54,30.97 119.42,31.09 118.39,31.09 117.5,30.2 117.5,28.12 122.48,23.14 122.48,15.09 123.33,14.23 123.33,4.46 123.18,4.3 122.68,4.3 122.53,4.46 J24.C4
ENET1G_2_MDI0P: length 33.1
  IN2 w0.152: J22.B1 119.57,30.33 119.5,30.54 119.3,30.63 119.26,30.68 118.55,30.68 117.91,30.03 117.91,28.29 122.89,23.31 122.89,15.26 123.74,14.4 123.74,4.29 123.35,3.9 122.68,3.9 122.53,3.74 J24.B4
ENET1G_2_MDI1N: length 35.7
  IN1 w0.152: J22.B6 124.31,30.78 120.8,30.78 120.04,30.02 120.04,28.96 122.43,26.57 122.43,19.96 121.26,18.8 121.26,3.19 121.07,3 120.69,3 120.53,3.17 J24.B5
ENET1G_2_MDI1P: length 35
  IN1 w0.152: J24.A5 120.53,2.4 120.73,2.6 121.24,2.6 121.67,3.02 121.67,18.63 122.83,19.8 122.83,26.74 120.45,29.12 120.45,29.85 120.97,30.38 122.89,30.38 123.09,30.18 123.09,29.64 122.83,29.38 J22.B3
ENET1G_2_MDI2N: length 30.2
  BOTTOM w0.147: J24.E5 120.53,7.3 120.68,7.15 121.23,7.15 121.49,7.42 121.49,14.02 120.22,15.29 120.22,23.62 120.59,24 120.59,24.23 120.91,24.54 121.14,24.54 121.45,24.85 121.45,25.08 121.76,25.39 121.99,25.39 122.3,25.71 122.3,25.93 122.61,26.25 122.84,26.25 125.15,28.55 125.15,30.1 124.54,30.7 123.95,30.7 123.91,30.67 123.74,30.58 123.67,30.38 J22.B5
ENET1G_2_MDI2P: length 30.9
  BOTTOM w0.147: J24.D5 120.53,6.65 120.73,6.85 121.35,6.85 121.79,7.29 121.79,14.15 120.52,15.42 120.52,23.5 125.45,28.42 125.45,30.23 124.67,31.01 123.82,31.01 123.73,30.92 123.6,30.85 123.4,30.92 J22.B4
ENET1G_2_MDI3N: length 43.5
  IN1 w0.152: J24.C6 118.53,4.47 118.69,4.3 118.99,4.3 119.33,4.64 119.33,17.49 119.58,17.75 119.58,27.03 117.65,28.96 117.65,31.95 119.71,34.01 125.68,34.01 127.1,32.59 127.1,31.03 127.16,30.97 127.3,30.9 127.5,30.97 J22.B8
ENET1G_2_MDI3P: length 43.3
  IN1 w0.152: J22.B7 127.19,30.33 127.12,30.54 126.92,30.63 126.7,30.86 126.7,32.42 125.51,33.6 119.88,33.6 118.06,31.78 118.06,29.12 119.99,27.19 119.99,17.58 119.74,17.33 119.74,4.47 119.16,3.9 118.69,3.9 118.53,3.73 J24.B6
ENET1G_3_MDI0N: length 39.2
  IN2 w0.152: J23.A2 348.19,36.93 348.39,37 348.47,36.96 349.93,35.5 349.93,29.47 349.76,29.3 349.76,28.84 349.93,28.67 349.93,28.22 349.76,28.04 349.76,27.59 349.93,27.41 349.93,26.96 349.76,26.78 349.76,26.33 349.93,26.15 349.93,22.03 351.84,20.13 351.84,3.78 351.05,3 350.03,3 J7.B1
ENET1G_3_MDI0P: length 39.9
  IN2 w0.152: J7.A1 350.03,2.6 351.22,2.6 352.24,3.62 352.24,20.29 350.34,22.2 350.34,35.67 348.71,37.29 348.57,37.36 348.5,37.57 J23.A1
